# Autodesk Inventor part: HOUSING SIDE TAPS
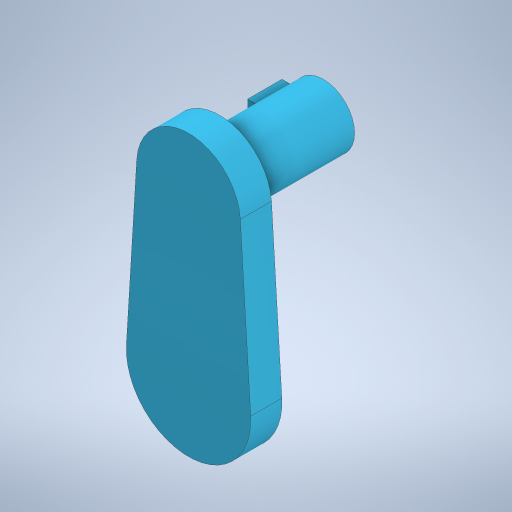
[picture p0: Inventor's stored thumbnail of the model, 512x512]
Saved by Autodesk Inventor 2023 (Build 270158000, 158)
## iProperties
Created: 2025-07
Part Number: HOUSING SIDE TAPS
Material: Generic
Document SubType Name: Modeling
Designer: erjon
Density: 1 g/cm^3
Appearance: Default
Author: erjon
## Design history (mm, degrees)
feature "Base1"
body "Solid1"
